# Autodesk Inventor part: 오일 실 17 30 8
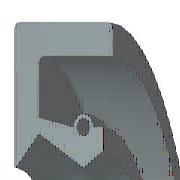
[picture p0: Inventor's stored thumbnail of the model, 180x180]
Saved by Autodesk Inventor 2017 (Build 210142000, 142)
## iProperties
Created: 2012-02
Part Number: 오일 실 17 30 8
Material: 고무
Description: 오일-실
Document SubType Name: Modeling
Standard: KS B 2804
Designer: mduedu
Standards Organization: KS
Language: ko-KR
Size Designation: D - 17 30 8
Categories: <MemberInstance><Categories><Category DisplayName="샤프트 부품" InternalName="7f7aeb1f-a693-4053-b835-cee3144e0d98" Mnemonic="SHFT"><Category DisplayName="실링" Intern
Density: 0.93 g/cm^3
Mass: 2.05499 g
Surface Area: 29.2219 cm^2
Volume: 2.20967 cm^3
Appearance: 고무 - 검은색 - 버전 1.1
IsCustomPart: 1
Author: mduedu
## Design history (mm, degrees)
revolve "본체" stored, may be unused: angle "d17" = 90 deg
revolve "스프링1" stored, may be unused: angle "d18" = 90 deg
fillet "모깎기3" dims "d43" = 0.5
body "Solid1"
sketch "스케치1"
  geometry: L1 (0, 15)-(8, 15); L2 (8, 13.25)-(1.75, 13.25); L3 (1.75, 10.25)-(4.9, 8.5); L4 (4.9, 8.5)-(0, 8.5); L5 (0, 0)-(9.586, 0) reference; L6 (4.9, 8.5)-(6.3, 9.375); L7 (0, 18)-(0, -3) reference; L8 (-1.941, 0)-(11.507, 0) reference; L9 (4.2, 10.6)-(1.75, 11.21); L10 (1.75, 11.21)-(1.75, 13.25); L11 (0, 15)-(0, 8.588); L12 (4.9, 8.5)-(0, 8.5); L13 (1.75, 10.25)-(0.152, 8.528); L14 (8, 15)-(8, 13.25); L15 (5.6, 10.6)-(6.3, 10.6); L16 (6.3, 10.6)-(6.3, 9.375); C1 r 0.455 at (4.9, 10.6); A1 r 0.7 centre (4.9, 10.6) between (5.6, 10.6) and (4.2, 10.6); A2 r 0.088 centre (0.088, 8.588) between (0, 8.588) and (0.152, 8.528); 1 further point
  constraints: 28 end point, 5 horizontal alignment, 5 point on line, 4 point on circle, 4 vertical alignment, 3 centre point, 3 tangent, 2 collinear, 2 horizontal, 2 perpendicular, 1 coincident, 1 parallel
  dimensions: "d0" = 30 diameter of L1 L5 (= SD2); "d1" = 1.75 distance of L1.end L2.start (= SD); "d2" = 0.91 diameter of C1 (= SPDI); "d3" = 1.4 diameter of A1 (= SPDA); "d4" = 17 diameter of L3.end L5 (= NND); "d5" = 20.5 diameter of L3.start L5 (= TKDM); "d7" = 22.42 diameter of L9.end L5 (= TKDM + 0.24 x SWDT); "d8" = 1.75 distance between parallel lines of L11 L10 (= SD); "d9" = 4.9 distance from line of L11 C1.centre (= SPDST); "d10" = 21.2 diameter of C1.centre L5 (= HLDM); "d11" = 0.0875 radius of A2 (= 0.25 x LAB); "d12" = 6.3 distance between parallel lines of L11 L16 (= SDI); "d13" = 18.75 diameter of L6.end L5 (= ABDM); "d14" = 8 distance from line of L11 L1.end (= SWDT)
fillet "모깎기1" dims "d6" = 0.3 (= RR)
other parameters: "SD2" = 30 [user parameter; used in 1 equation term], "SWDT" = 8 [user parameter; used in 2 equation terms], "RR" = 0.3 [user parameter; used in 1 equation term], "SD" = 1.75 [user parameter; used in 2 equation terms], "NND" = 17 [user parameter; used in 1 equation term], "SPDA" = 1.4 [user parameter; used in 1 equation term], "SPDI" = 0.91 [user parameter; used in 1 equation term], "TKDM" = 20.5 [user parameter; used in 2 equation terms], "HLDM" = 21.2 [user parameter; used in 1 equation term], "ABDM" = 18.75 [user parameter; used in 1 equation term], "SDI" = 6.3 [user parameter; used in 1 equation term], "SPDST" = 4.9 [user parameter; used in 1 equation term], "LAB" = 0.35 [user parameter; used in 1 equation term], "d15" = 0, "d16" = 0, "d19" = 0
